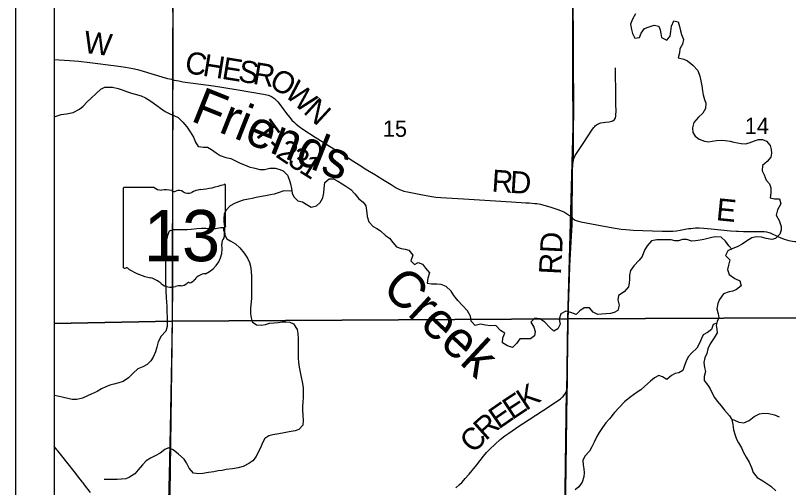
# Model space of a CAD drawing. Extents: x 0 to 34, y 0 to 22.
# Drawn here: x 2 to 3.99, y 14.823 to 16.037 of the extents above; entities that cross this region are included whole.
import ezdxf

# ---------------------------------------------------------------- set-up
doc = ezdxf.new("R2010")
doc.units = 0
for name, color, linetype in [('Default', 7, 'Continuous'), ('GM_X_County_Road', 7, 'Continuous'), ('GM_X_Minor_River', 7, 'Continuous'), ('GM_X_Minor_River_Text', 7, 'Continuous'), ('GM_X_Section', 7, 'Continuous'), ('GM_X_Section_Text', 7, 'Continuous'), ('GM_X_State_Location', 7, 'Continuous'), ('GM_X_State_Route', 7, 'Continuous'), ('GM_X_State_Shield', 7, 'Continuous'), ('GM_X_Township_Road', 7, 'Continuous'), ('GM_X_Township_Road_Text', 7, 'Continuous'), ('SH_Cut_Line', 7, 'Continuous'), ('SH_Data', 7, 'Continuous')]:
    doc.layers.add(name, color=color, linetype=linetype)

msp = doc.modelspace()

# ---------------------------------------------------------------- linework, layer by layer
at = {"layer": 'Default'}
for points in [[(2.1, 18.2607), (2.1, 14.1)], [(3.4335, 16.269), (3.4355, 15.6642), (3.4344, 15.6593), (3.4337, 15.6531), (3.4331, 15.6376), (3.4326, 15.6065), (3.4319, 15.5382), (3.4322, 15.5196), (3.4326, 15.5166), (3.4325, 15.5111), (3.4325, 15.5073), (3.432, 15.498), (3.4302, 15.4701), (3.4263, 15.3925), (3.4253, 15.3614), (3.4227, 15.2869), (3.4218, 15.2465), (3.4213, 15.1844), (3.4204, 15.1316), (3.4201, 15.0852), (3.4199, 15.0787), (3.4197, 15.0762), (3.4192, 15.0738), (3.4184, 15.0709), (3.4076, 14.2404)], [(3.4076, 14.2404), (3.4184, 15.0709), (3.4192, 15.0738), (3.4197, 15.0762), (3.4199, 15.0787), (3.4201, 15.0852), (3.4204, 15.1316), (3.4213, 15.1844), (3.4218, 15.2465), (3.4227, 15.2869), (3.4253, 15.3614), (3.4263, 15.3925), (3.4302, 15.4701), (3.432, 15.498), (3.4325, 15.5073), (3.4325, 15.5111), (3.4326, 15.5166), (3.4322, 15.5196), (3.4319, 15.5382), (3.4326, 15.6065), (3.4331, 15.6376), (3.4337, 15.6531), (3.4344, 15.6593), (3.4355, 15.6642), (3.4335, 16.269)]]:
    msp.add_lwpolyline(points, dxfattribs=at)
for points in [[(2.1, 16.2572), (2.1, 15.2441), (2.4044, 15.2506), (2.4062, 16.2575), (2.4062, 16.2613)], [(2.1, 15.2441), (2.1, 14.2363), (2.3909, 14.2388), (2.4044, 15.2506)]]:
    msp.add_lwpolyline(points, close=True, dxfattribs=at)
at = {"layer": 'GM_X_County_Road'}
msp.add_lwpolyline([(2.1935, 14.81), (2.1781, 14.8294), (2.1742, 14.8343), (2.1723, 14.8367), (2.1569, 14.8563), (2.155, 14.8587), (2.1319, 14.888), (2.1281, 14.8929), (2.1261, 14.8953), (2.1087, 14.9171), (2.1067, 14.9196), (2.1048, 14.922), (2.1, 14.9281)], dxfattribs=at)
at = {"layer": 'GM_X_Minor_River'}
for points in [[(3.5962, 16.0407), (3.5879, 16.0267), (3.583, 16.0138), (3.5856, 16.0009), (3.5883, 15.9903), (3.5939, 15.9778), (3.6061, 15.98), (3.6102, 15.9914), (3.619, 16.0028), (3.6311, 16.0077), (3.644, 16.0119), (3.6561, 16.0093), (3.6592, 15.9998), (3.6614, 15.9903), (3.6633, 15.9797), (3.6766, 15.9732), (3.6853, 15.9835), (3.6868, 15.9956), (3.6887, 16.0093), (3.6948, 16.0225), (3.7058, 16.0199), (3.7096, 16.0085), (3.7118, 15.9975), (3.7141, 15.9876), (3.7194, 15.9747), (3.7171, 15.963), (3.7099, 15.9508), (3.7092, 15.9402), (3.7061, 15.9273), (3.7201, 15.9243), (3.7296, 15.9201), (3.7433, 15.9088), (3.7561, 15.8947), (3.7618, 15.8807), (3.7641, 15.8682), (3.7664, 15.856), (3.7682, 15.8428), (3.7698, 15.8325), (3.7739, 15.8204), (3.7769, 15.8109), (3.7762, 15.7976), (3.769, 15.7855), (3.758, 15.7752), (3.7458, 15.7616), (3.7428, 15.7479), (3.7439, 15.7358), (3.7492, 15.7259), (3.7602, 15.7187), (3.7735, 15.7134), (3.7837, 15.7119), (3.7936, 15.7134), (3.8042, 15.7153), (3.8175, 15.7161), (3.8269, 15.7153), (3.8394, 15.713), (3.8489, 15.7108), (3.8584, 15.7089), (3.8683, 15.707), (3.8789, 15.7066), (3.8887, 15.7089)], [(2.1, 15.7756), (2.107, 15.7789), (2.1176, 15.7819), (2.1317, 15.7838), (2.1484, 15.7872), (2.1647, 15.7956), (2.1746, 15.8032), (2.1848, 15.8142), (2.1947, 15.8237), (2.2076, 15.8363), (2.2201, 15.8469), (2.23, 15.8519), (2.2395, 15.8522), (2.2497, 15.8519), (2.2645, 15.8488), (2.2748, 15.845), (2.2881, 15.8405), (2.2987, 15.8371), (2.3082, 15.834), (2.3234, 15.8299), (2.3344, 15.8249), (2.3484, 15.8162), (2.3636, 15.8052), (2.3731, 15.7984), (2.3857, 15.79), (2.3974, 15.7836), (2.4092, 15.7786), (2.4187, 15.7741), (2.4305, 15.7623), (2.4411, 15.7501), (2.4498, 15.7376), (2.4586, 15.7236), (2.4631, 15.711), (2.47, 15.7), (2.4844, 15.6981), (2.4939, 15.6977), (2.5045, 15.6921), (2.5167, 15.6833), (2.5266, 15.6765), (2.5414, 15.6712), (2.5547, 15.6685), (2.5645, 15.6636), (2.5786, 15.6564), (2.5892, 15.6522), (2.6018, 15.6473), (2.6158, 15.6435), (2.6287, 15.6404), (2.6409, 15.6408), (2.6549, 15.6435), (2.6682, 15.6439), (2.6781, 15.6416), (2.6895, 15.6374), (2.7001, 15.626), (2.7047, 15.615), (2.7081, 15.6036), (2.7104, 15.5919), (2.7123, 15.5797), (2.7168, 15.5698), (2.7271, 15.56), (2.7392, 15.5573), (2.7487, 15.5516), (2.7616, 15.544), (2.7749, 15.5471), (2.7844, 15.5558), (2.7912, 15.5672), (2.7939, 15.5805), (2.795, 15.5919), (2.7965, 15.6067), (2.8079, 15.6166), (2.8189, 15.6162), (2.8299, 15.6105), (2.8406, 15.6037), (2.8508, 15.5972), (2.863, 15.5893), (2.874, 15.5775), (2.8835, 15.5653), (2.8949, 15.5566), (2.9017, 15.5471), (2.9048, 15.5293), (2.9055, 15.5194), (2.9097, 15.5061), (2.9204, 15.4939), (2.9298, 15.4886), (2.9397, 15.4829), (2.9526, 15.4708), (2.9625, 15.4639)], [(3.8887, 15.7089), (3.9024, 15.7138), (3.913, 15.7176), (3.9228, 15.7172), (3.9335, 15.7134), (3.9425, 15.7021), (3.9456, 15.6918), (3.946, 15.6823), (3.9444, 15.6725), (3.9353, 15.6611), (3.9232, 15.6505), (3.9217, 15.6372), (3.9273, 15.6266), (3.9323, 15.6133), (3.941, 15.6038), (3.9444, 15.5936), (3.9444, 15.5803), (3.9429, 15.5674), (3.9542, 15.5651), (3.9671, 15.5648), (3.9701, 15.5522), (3.9618, 15.5363), (3.958, 15.523), (3.9656, 15.509), (3.9709, 15.4938), (3.9709, 15.484), (3.9678, 15.4745), (3.9561, 15.4631), (3.9466, 15.4608), (3.9322, 15.4627), (3.9201, 15.4665), (3.9064, 15.4673), (3.8958, 15.4646), (3.8818, 15.4563), (3.8704, 15.4487), (3.8575, 15.4418), (3.8469, 15.4373), (3.8336, 15.4312), (3.8275, 15.4191), (3.8389, 15.4077), (3.8355, 15.3944), (3.8325, 15.3834), (3.8374, 15.3702), (3.8518, 15.3603), (3.865, 15.3542), (3.8677, 15.3413), (3.8563, 15.3315), (3.8465, 15.3277), (3.837, 15.3254), (3.8226, 15.3205), (3.8123, 15.3064), (3.8081, 15.2954), (3.8055, 15.2825), (3.8089, 15.2689), (3.8104, 15.259), (3.8059, 15.2495), (3.804, 15.2393), (3.8055, 15.2298), (3.8062, 15.2203), (3.7982, 15.2071), (3.7884, 15.1923), (3.7823, 15.1794), (3.7793, 15.1668), (3.7747, 15.1562), (3.7717, 15.1445), (3.7736, 15.1308), (3.7762, 15.121), (3.7732, 15.1077), (3.7732, 15.0978), (3.7826, 15.0861), (3.7879, 15.0762), (3.7925, 15.0667), (3.7993, 15.0538), (3.8065, 15.0443), (3.8164, 15.033), (3.8255, 15.0212), (3.838, 15.0068), (3.8436, 14.9973), (3.847, 14.9844), (3.8485, 14.9711), (3.8523, 14.9571), (3.8561, 14.9472), (3.8614, 14.9374), (3.869, 14.9245), (3.8739, 14.9127), (3.8807, 14.901), (3.8883, 14.8877), (3.8944, 14.8744), (3.8993, 14.8611), (3.9091, 14.8483), (3.9235, 14.8399), (3.9345, 14.8331), (3.9444, 14.8259), (3.9573, 14.8141)], [(2.7113, 15.5857), (2.7043, 15.5846), (2.6906, 15.5854), (2.6766, 15.5808), (2.6659, 15.5774), (2.6565, 15.5755), (2.6439, 15.5728), (2.6329, 15.5713), (2.62, 15.5683), (2.6094, 15.5656), (2.5999, 15.5641), (2.5862, 15.5618), (2.5741, 15.5572), (2.5635, 15.5534), (2.5528, 15.5473), (2.5411, 15.5352), (2.5373, 15.5257), (2.5361, 15.5154), (2.5365, 15.5059), (2.5377, 15.493), (2.538, 15.4835), (2.5388, 15.4717), (2.5437, 15.4619), (2.554, 15.4562), (2.5665, 15.4497), (2.5779, 15.4387), (2.5889, 15.425), (2.5969, 15.4125), (2.6022, 15.4015), (2.6053, 15.392), (2.6068, 15.3787), (2.6072, 15.3643), (2.6076, 15.3532), (2.608, 15.3384), (2.608, 15.3225), (2.6072, 15.3092), (2.605, 15.2833), (2.605, 15.2689), (2.6065, 15.259), (2.6095, 15.2488), (2.6205, 15.2412), (2.6327, 15.2404), (2.6437, 15.242), (2.6543, 15.245), (2.6657, 15.2465), (2.676, 15.2469), (2.6862, 15.2484), (2.6968, 15.2488), (2.7063, 15.2477), (2.7158, 15.2435), (2.725, 15.2291), (2.7269, 15.2184), (2.7276, 15.2051), (2.7276, 15.1554), (2.7284, 15.1451), (2.7307, 15.1318), (2.733, 15.1189), (2.7353, 15.1064), (2.7383, 15.0942), (2.7406, 15.0798), (2.7406, 15.0661), (2.7402, 15.0551), (2.7395, 15.0414), (2.7391, 15.0319), (2.7391, 15.0213), (2.7399, 15.0084), (2.741, 14.9951), (2.7395, 14.9825), (2.7292, 14.9719), (2.7198, 14.9685), (2.7049, 14.9654), (2.6913, 14.9635), (2.678, 14.9605), (2.6628, 14.9578), (2.6526, 14.9551), (2.6419, 14.9483), (2.6362, 14.9377), (2.6309, 14.9244), (2.6249, 14.9133), (2.6196, 14.9027), (2.6108, 14.8913), (2.6006, 14.8841), (2.5862, 14.8769), (2.5736, 14.8734), (2.5588, 14.8708), (2.5425, 14.8689), (2.5319, 14.8666), (2.522, 14.8654), (2.5102, 14.8631), (2.4969, 14.8609), (2.4825, 14.8586), (2.4719, 14.8578), (2.4582, 14.8597), (2.4472, 14.8719), (2.44, 14.8859), (2.4343, 14.8958), (2.4199, 14.9079), (2.4062, 14.9197), (2.3936, 14.925), (2.3842, 14.9201), (2.3728, 14.9106)], [(2.5377, 15.4908), (2.5285, 15.4903), (2.5153, 15.4877), (2.5016, 15.4881), (2.4898, 15.4888), (2.4792, 15.4884), (2.467, 15.4877), (2.4526, 15.4861), (2.4424, 15.4857), (2.4317, 15.4857), (2.4181, 15.4854), (2.4071, 15.485), (2.3953, 15.4819), (2.3915, 15.4709), (2.3892, 15.4599), (2.387, 15.4447), (2.3866, 15.4341), (2.387, 15.4204), (2.387, 15.4094), (2.3866, 15.3995), (2.3866, 15.3877), (2.3862, 15.371), (2.3862, 15.3611), (2.3866, 15.3474), (2.387, 15.3379), (2.387, 15.3277), (2.3882, 15.311), (2.3889, 15.2996), (2.3897, 15.2889), (2.3897, 15.2741), (2.3901, 15.2605), (2.3901, 15.251), (2.3905, 15.2365), (2.3867, 15.2244), (2.3749, 15.2114), (2.3677, 15.1974), (2.3639, 15.1837), (2.3601, 15.1712), (2.3544, 15.1575), (2.3487, 15.148), (2.3389, 15.1389), (2.3279, 15.1328), (2.3153, 15.1275), (2.3032, 15.1168), (2.2911, 15.1047), (2.277, 15.0952), (2.2664, 15.0921), (2.2535, 15.0887), (2.2429, 15.086), (2.2326, 15.0815), (2.2216, 15.0765), (2.2102, 15.0697), (2.195, 15.0628), (2.1852, 15.0586), (2.1723, 15.0526), (2.1582, 15.0488), (2.1461, 15.0487), (2.1233, 15.0541), (2.1088, 15.0575), (2.1, 15.059)], [(2.9625, 15.4639), (2.9712, 15.4529), (2.9804, 15.4419), (2.9925, 15.4374), (3.0028, 15.4355), (3.0123, 15.4328), (3.0225, 15.4199), (3.018, 15.4055), (3.0271, 15.396), (3.0366, 15.4013), (3.0476, 15.3967), (3.0559, 15.3869), (3.0654, 15.3743), (3.0613, 15.361), (3.0598, 15.3481), (3.0708, 15.3462), (3.0844, 15.3462), (3.0947, 15.3459), (3.108, 15.3402)], [(3.8438, 15.4359), (3.8363, 15.4441), (3.8276, 15.4563), (3.8162, 15.4661), (3.8029, 15.4669), (3.7923, 15.4654), (3.7825, 15.4631), (3.7718, 15.46), (3.7624, 15.4585), (3.7506, 15.4574), (3.7411, 15.4562), (3.7282, 15.4608), (3.7173, 15.4608), (3.707, 15.4566), (3.6975, 15.4574), (3.6881, 15.4597), (3.6513, 15.4596), (3.6376, 15.457), (3.6259, 15.4445), (3.6194, 15.4327), (3.613, 15.4168), (3.6058, 15.4069), (3.5917, 15.3925), (3.583, 15.3807), (3.5807, 15.369), (3.5807, 15.358), (3.58, 15.3481), (3.5777, 15.3386), (3.5671, 15.3254), (3.5527, 15.3163), (3.5504, 15.3056), (3.5538, 15.2916), (3.5504, 15.2779), (3.5409, 15.2723), (3.5314, 15.27), (3.52, 15.2692), (3.5083, 15.2681), (3.4988, 15.2673), (3.4871, 15.2738), (3.4772, 15.2851), (3.4643, 15.2851), (3.4526, 15.2768), (3.4431, 15.2673), (3.4298, 15.2726), (3.4169, 15.2757), (3.4037, 15.2692), (3.3995, 15.2552), (3.4025, 15.2423), (3.3957, 15.2305), (3.3858, 15.2244), (3.3752, 15.2339), (3.3623, 15.2476), (3.3502, 15.2563), (3.3373, 15.2582), (3.3263, 15.248), (3.3343, 15.2351), (3.3377, 15.2241), (3.3358, 15.2123), (3.3259, 15.2051), (3.3119, 15.2051), (3.2986, 15.2047), (3.2895, 15.1929), (3.2793, 15.1823), (3.2664, 15.1869), (3.2535, 15.1948), (3.2547, 15.2077), (3.2596, 15.2195), (3.2486, 15.2263), (3.2369, 15.2392), (3.2232, 15.2381), (3.2103, 15.24), (3.1967, 15.2426), (3.183, 15.2396), (3.1728, 15.2506), (3.1717, 15.2635), (3.1633, 15.2768), (3.1508, 15.2908), (3.1391, 15.3037), (3.1281, 15.3162), (3.1213, 15.3276), (3.108, 15.3402)], [(3.8051, 15.2453), (3.796, 15.2419), (3.7914, 15.2291), (3.7816, 15.2215), (3.7706, 15.215), (3.7656, 15.2055), (3.7611, 15.1938), (3.7539, 15.1809), (3.741, 15.1691), (3.7319, 15.1589), (3.7266, 15.1479), (3.722, 15.1361), (3.7175, 15.1236), (3.708, 15.1175), (3.6985, 15.116), (3.6886, 15.1103), (3.6769, 15.1001), (3.6655, 15.1069), (3.656, 15.1107), (3.6447, 15.105), (3.6348, 15.0963), (3.62, 15.0834), (3.6098, 15.0739), (3.6003, 15.0678), (3.5813, 15.0542), (3.5681, 15.0428), (3.5537, 15.0287), (3.5423, 15.0155), (3.5294, 14.9995), (3.5199, 14.9885), (3.5112, 14.9772), (3.5025, 14.9639), (3.4968, 14.954), (3.4895, 14.9396), (3.4839, 14.9271), (3.4778, 14.9161), (3.466, 14.9028), (3.4607, 14.8922), (3.4615, 14.8808), (3.4634, 14.8702), (3.4637, 14.86), (3.4633, 14.8501), (3.4588, 14.8364), (3.4501, 14.8239), (3.4406, 14.8167)], [(3.8436, 14.9973), (3.8493, 14.9969), (3.8618, 14.9909), (3.8751, 14.9886), (3.8887, 14.995), (3.9013, 15.0053), (3.9153, 15.0121), (3.9267, 15.014), (3.9392, 15.0129), (3.9536, 15.0091), (3.9661, 15.0045)], [(2.3728, 14.9106), (2.3599, 14.9037), (2.3473, 14.898), (2.3367, 14.8912), (2.3272, 14.8809), (2.3162, 14.868), (2.3071, 14.8581), (2.2935, 14.849), (2.284, 14.8452), (2.2619, 14.8429), (2.2384, 14.8429), (2.2282, 14.8433)]]:
    msp.add_lwpolyline(points, dxfattribs=at)
at = {"layer": 'GM_X_Section'}
for points in [[(2.4062, 16.2575), (3.434, 16.2663), (3.4363, 15.7808), (3.4219, 15.2567), (2.4044, 15.2506)], [(3.434, 16.2663), (4.4273, 16.2727), (4.4235, 15.2608), (3.4219, 15.2567), (3.4363, 15.7808)], [(3.4219, 15.2567), (3.4079, 14.2395), (2.3909, 14.2388), (2.4044, 15.2506)], [(4.4235, 15.2608), (4.4107, 14.2482), (3.4079, 14.2395), (3.4219, 15.2567)]]:
    msp.add_lwpolyline(points, close=True, dxfattribs=at)
at = {"layer": 'GM_X_State_Route'}
msp.add_lwpolyline([(2.3932, 14.5756), (2.3938, 14.5861), (2.3937, 14.6481), (2.3938, 14.6916), (2.3943, 14.7196), (2.3951, 14.7881), (2.3964, 14.8563), (2.3989, 14.9744), (2.4025, 15.1546), (2.4041, 15.2602), (2.4048, 15.341), (2.4051, 15.4125), (2.4055, 15.6176), (2.4052, 15.6612), (2.4053, 15.7233), (2.4056, 15.7606), (2.4055, 15.8197), (2.4057, 15.8713), (2.4056, 15.9067), (2.4056, 15.9968), (2.4055, 16.0932)], dxfattribs=at)
at = {"layer": 'GM_X_State_Shield'}
for p, q in [((2.277, 15.5905), (2.277, 15.3904)), ((2.3568, 15.594), (2.2796, 15.594)), ((2.5406, 15.4942), (2.5406, 15.5989)), ((2.5406, 15.4943), (2.5406, 15.4942))]:
    msp.add_line(p, q, dxfattribs=at)
for centre, radius, start, end in [((2.4467, 15.8668), 0.2796, 275.8445, 288.9065), ((2.5377, 15.5994), 0.00294, 351.8621, 97.738), ((2.28, 15.5909), 0.00305, 98.1301, 188.1301), ((2.3752, 15.6172), 0.0296, 231.6195, 271.1119), ((2.385, 15.4816), 0.1064, 80.4867, 94.9883), ((2.4091, 15.592), 0.00855, 219.7921, 297.1024), ((2.4217, 15.5689), 0.0178, 54.4667, 119.1411), ((2.4446, 15.6006), 0.0214, 233.8562, 294.8282), ((2.4824, 15.5328), 0.0563, 97.3462, 120.7689), ((2.54, 15.4866), 0.00454, 107.944, 210.337), ((2.5111, 15.4733), 0.0273, 340.033, 23.6496), ((2.5375, 15.4938), 0.00314, 289.6038, 7.7341), ((2.5512, 15.4504), 0.0198, 136.8065, 186.9296), ((2.4624, 15.4371), 0.0699, 292.3089, 8.9858), ((2.28, 15.39), 0.00308, 171.9584, 258.3066), ((2.2805, 15.4104), 0.0235, 267.339, 280.6039), ((2.2853, 15.3789), 0.00848, 29.7484, 93.2717), ((2.3924, 15.5587), 0.2019, 240.4129, 257.1985), ((2.4919, 15.3342), 0.0383, 94.4031, 142.5768), ((2.3322, 15.3005), 0.0632, 47.1842, 75.836), ((2.4005, 15.3779), 0.0401, 230.7004, 286.2918), ((2.4266, 15.3629), 0.0214, 268.777, 315.5493), ((2.4459, 15.3435), 0.00601, 65.7517, 132.6484), ((2.4433, 15.371), 0.0226, 282.8732, 323.2771), ((2.4236, 15.3087), 0.0329, 85.6951, 111.2099)]:
    msp.add_arc(centre, radius, start, end, dxfattribs=at)
at = {"layer": 'GM_X_Township_Road'}
for points in [[(2.1, 15.9235), (2.1387, 15.921), (2.1635, 15.9191), (2.1912, 15.916), (2.259, 15.9073), (2.2836, 15.9037), (2.3019, 15.9004), (2.3141, 15.8977), (2.329, 15.8936), (2.3765, 15.8789), (2.3915, 15.8749), (2.402, 15.8724), (2.4057, 15.8713)], [(3.4357, 15.6637), (3.4359, 15.6648), (3.438, 15.6707), (3.4408, 15.6762), (3.4456, 15.6842), (3.461, 15.7076), (3.4851, 15.7438), (3.4889, 15.7488), (3.491, 15.7511), (3.4933, 15.7532), (3.4957, 15.7551), (3.4983, 15.7568), (3.501, 15.7582), (3.5039, 15.7594), (3.5068, 15.7604), (3.5129, 15.7617), (3.5191, 15.7624), (3.528, 15.7633), (3.5313, 15.7637), (3.5355, 15.7649), (3.5376, 15.7658), (3.5419, 15.7692), (3.5442, 15.7735), (3.5455, 15.7773), (3.5466, 15.7936), (3.5458, 15.8053), (3.5457, 15.8486), (3.5448, 15.8798), (3.5442, 15.9017)], [(2.4057, 15.8713), (2.4088, 15.8705), (2.4148, 15.8692), (2.4204, 15.8681), (2.4312, 15.8662), (2.5096, 15.8554), (2.5682, 15.8463), (2.6382, 15.8343), (2.6473, 15.8324), (2.6504, 15.8318), (2.6532, 15.8307), (2.6589, 15.8282), (2.6641, 15.8249), (2.6666, 15.823), (2.6712, 15.8189), (2.6754, 15.8143), (2.6813, 15.8071), (2.6978, 15.7845), (2.7054, 15.7747), (2.7114, 15.7676), (2.7179, 15.7609), (2.7226, 15.7568), (2.7299, 15.7511), (2.7401, 15.744), (2.7713, 15.7236), (2.808, 15.7006), (2.8236, 15.6913), (2.8394, 15.6816), (2.8712, 15.6614), (2.8918, 15.648), (2.9006, 15.6423), (2.9264, 15.6266), (2.9296, 15.625), (2.9457, 15.6149), (2.9667, 15.6016), (2.98, 15.5936), (2.9883, 15.5894), (2.994, 15.587), (2.9999, 15.585), (3.0089, 15.5827), (3.0394, 15.5767), (3.0668, 15.5716), (3.0822, 15.5695), (3.0946, 15.5683), (3.1534, 15.5647), (3.2216, 15.561), (3.2765, 15.5571), (3.314, 15.5548), (3.322, 15.5545), (3.3368, 15.5534), (3.3423, 15.5527), (3.3514, 15.5511), (3.3605, 15.5489), (3.3753, 15.5444), (3.396, 15.5375), (3.4076, 15.5333), (3.4133, 15.5307), (3.4187, 15.5277), (3.4238, 15.5242), (3.4285, 15.5202), (3.4328, 15.5161)], [(3.4328, 15.5161), (3.4324, 15.519), (3.4321, 15.5376), (3.4328, 15.606), (3.4333, 15.637), (3.434, 15.6526), (3.4346, 15.6588), (3.4357, 15.6637)], [(3.4189, 15.0713), (3.4194, 15.0732), (3.4199, 15.0756), (3.4201, 15.0781), (3.4203, 15.0847), (3.4206, 15.131), (3.4215, 15.1838), (3.422, 15.246), (3.4229, 15.2863), (3.4255, 15.3609), (3.4265, 15.392), (3.4304, 15.4696), (3.4322, 15.4975), (3.4327, 15.5067), (3.4327, 15.5105), (3.4328, 15.5161)], [(3.4328, 15.5161), (3.4353, 15.5137), (3.4378, 15.512), (3.4404, 15.5104), (3.4432, 15.5091), (3.4462, 15.508), (3.4491, 15.5072), (3.4552, 15.5058), (3.5102, 15.4956), (3.5438, 15.4895), (3.5591, 15.4872), (3.5715, 15.4859), (3.5901, 15.4847), (3.6645, 15.4819), (3.68, 15.4818), (3.6923, 15.4822), (3.7016, 15.483), (3.7108, 15.4842), (3.7321, 15.4883), (3.7383, 15.489), (3.7506, 15.4901), (3.7599, 15.4902), (3.7723, 15.4895), (3.7909, 15.4877), (3.8403, 15.4827), (3.8558, 15.4816), (3.8599, 15.4815)], [(3.8599, 15.4815), (3.8744, 15.481), (3.9147, 15.481), (3.9271, 15.4807), (3.9333, 15.48), (3.9394, 15.4788), (3.9423, 15.4779), (3.948, 15.4754), (3.9589, 15.4695), (3.9645, 15.4669), (3.979, 15.4615), (3.9909, 15.458), (3.9999, 15.4559), (4.0062, 15.4555), (4.0097, 15.4556), (4.0146, 15.4558)], [(3.287, 14.9742), (3.2878, 14.9748), (3.3567, 15.0194), (3.3842, 15.0378), (3.4026, 15.051), (3.4075, 15.0548), (3.4098, 15.0569), (3.4119, 15.0591), (3.4153, 15.0638), (3.4173, 15.0674), (3.4186, 15.0704), (3.4189, 15.0713)], [(3.1335, 14.8217), (3.1428, 14.8299), (3.1495, 14.8364), (3.1577, 14.8456), (3.1677, 14.8571), (3.1872, 14.8812), (3.2047, 14.903), (3.2128, 14.9124), (3.2213, 14.9213), (3.2344, 14.9338), (3.248, 14.9458), (3.2598, 14.9554), (3.2698, 14.9627), (3.287, 14.9742)]]:
    msp.add_lwpolyline(points, dxfattribs=at)
at = {"layer": 'SH_Cut_Line'}
msp.add_lwpolyline([(2.1, 20.9), (2.1, 14.1), (7.4893, 14.1)], dxfattribs=at)
at = {"layer": 'SH_Data'}
for p, q in [((2, 21), (2, 14)), ((2.1, 20.9), (2.1, 14.1))]:
    msp.add_line(p, q, dxfattribs=at)

# ---------------------------------------------------------------- texts
at = {"layer": 'GM_X_Minor_River_Text'}
for s, rotation, p in [('Friends', 338.2535, (2.4484, 15.7664)), ('Creek', 317.0868, (2.9397, 15.3296))]:
    msp.add_text(s, height=0.09473, rotation=rotation, dxfattribs=at).set_placement(p)
at = {"layer": 'GM_X_Section_Text'}
for s, p in [('15', (2.9456, 15.7245)), ('14', (3.8773, 15.7318))]:
    msp.add_text(s, height=0.04186, rotation=0, dxfattribs=at).set_placement(p)
at = {"layer": 'GM_X_State_Location'}
msp.add_text('13', height=0.000189, rotation=0, dxfattribs=at).set_placement((2.3581, 15.4634))
for s in ['s', 'r']:
    msp.add_text(s, height=0.000189, dxfattribs=at).set_placement((2.4058, 15.4772))
at = {"layer": 'GM_X_State_Shield'}
msp.add_text('13', height=0.13184, dxfattribs=at).set_placement((2.3306, 15.4045))
at = {"layer": 'GM_X_Township_Road_Text'}
for s, height, rotation, p in [('W', 0.0568, 352.6945, (2.1732, 15.9411)), ('C', 0.0568, 350.8162, (2.4337, 15.8894)), ('H', 0.0568, 350.8171, (2.4798, 15.882)), ('E', 0.0568, 350.818, (2.5291, 15.874)), ('S', 0.0568, 350.8095, (2.5711, 15.8672)), ('R', 0.0568, 350.539, (2.6088, 15.8611)), ('O', 0.0568, 329.6135, (2.6497, 15.8553)), ('W', 0.0568, 317.3619, (2.6903, 15.8319)), ('N', 0.0568, 317.3061, (2.7387, 15.7873)), ('T', 0.0568, 305.9716, (2.6096, 15.7402)), ('-', 0.0568, 316.0548, (2.6417, 15.6976)), ('2', 0.0568, 326.3253, (2.6672, 15.6745)), ('3', 0.0568, 327.7812, (2.6976, 15.6542)), ('1', 0.0568, 327.9685, (2.7274, 15.6354)), ('R', 0.0568, 356.1566, (3.2246, 15.5837)), ('D', 0.0568, 356.2836, (3.2713, 15.5806)), ('E', 0.0568, 354.404, (3.802, 15.5103)), ('RD', 0.05682, 87.0387, (3.4041, 15.3692)), ('K', 0.0568, 33.5882, (3.314, 15.0188)), ('E', 0.0568, 33.5142, (3.2785, 14.9953)), ('E', 0.0568, 34.7326, (3.2438, 14.9712)), ('R', 0.0568, 41.6559, (3.2104, 14.9414)), ('C', 0.0568, 47.573, (3.18, 14.908))]:
    msp.add_text(s, height=height, rotation=rotation, dxfattribs=at).set_placement(p)

doc.saveas('drawing.dxf')
